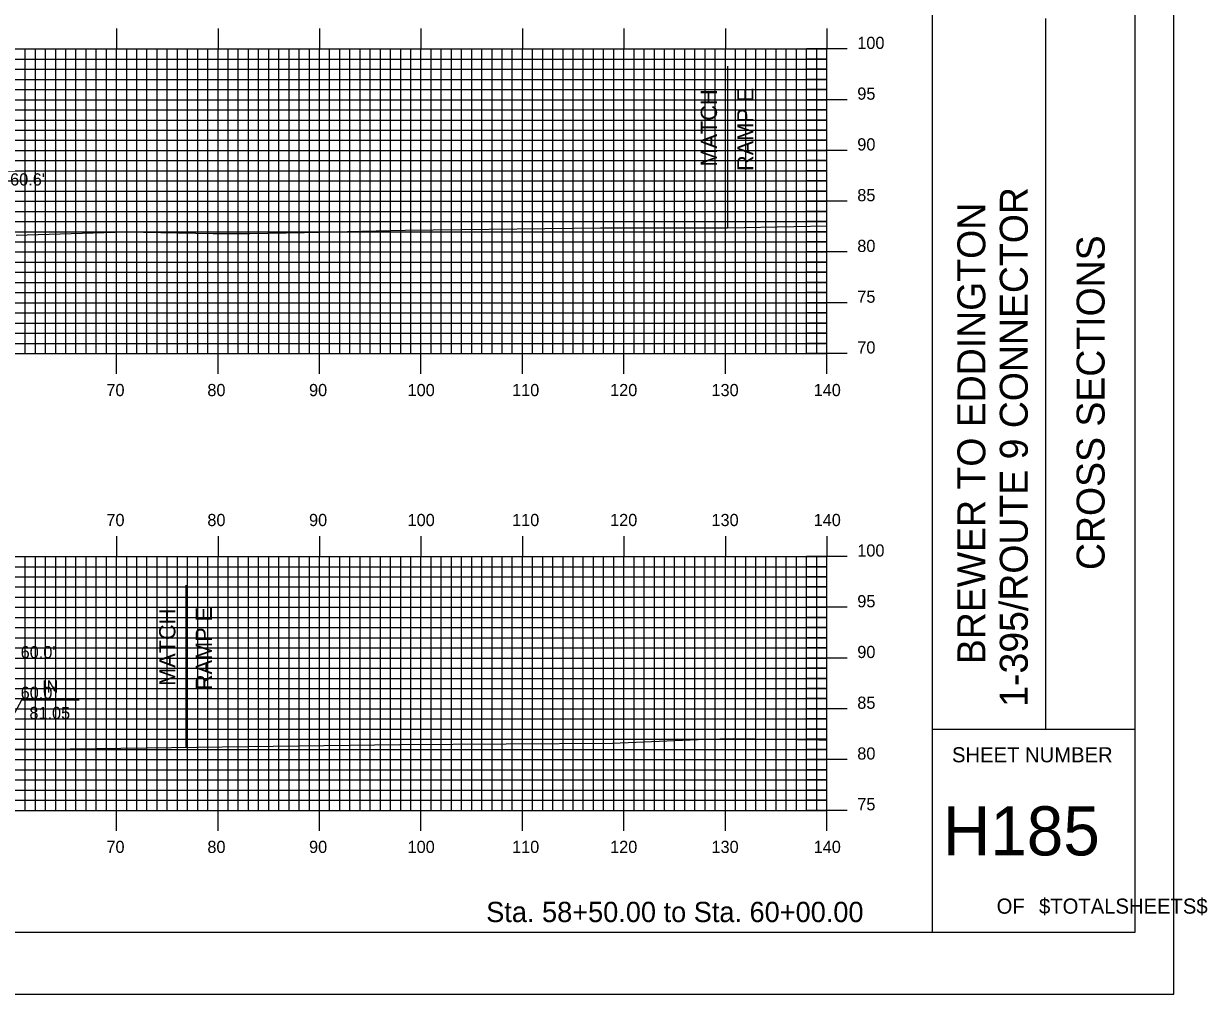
# Model space of a CAD drawing. Extents: x 1757462 to 1757806, y 442591 to 442811.
# Drawn here: x 1757689 to 1757805.6, y 442590.5 to 442686.2 of the extents above; entities that cross this region are included whole.
import ezdxf

# ---------------------------------------------------------------- set-up
doc = ezdxf.new("R2010")
doc.units = 0
for name, color, linetype in [('ANNOTATION', 7, 'Continuous'), ('BORDER', 7, 'Continuous'), ('D_Roadway_SubGrade', 7, 'Continuous'), ('D_Text_Standard', 7, 'Continuous'), ('H_V ANNOTATION', 7, 'Continuous'), ('MAJOR', 7, 'Continuous'), ('MINOR', 7, 'Continuous'), ('PLOT BOUNDARY', 7, 'Continuous'), ('S_Roadway_Centerline', 7, 'Continuous')]:
    doc.layers.add(name, color=color, linetype=linetype)

msp = doc.modelspace()

# ---------------------------------------------------------------- linework, layer by layer
at = {"layer": 'ANNOTATION'}
msp.add_lwpolyline([(1757694.44, 442619.53), (1757688.75, 442619.53), (1757686.11, 442614.72)], dxfattribs=at)
msp.add_lwpolyline([(1757694.44, 442619.53), (1757688.75, 442619.53), (1757686.11, 442614.72)], dxfattribs=at)
at = {"layer": 'BORDER'}
for p, q in [((1757778.51, 442596.67), (1757778.51, 442806.67)), ((1757789.69, 442616.67), (1757789.69, 442686.67)), ((1757778.51, 442616.67), (1757798.51, 442616.67))]:
    msp.add_line(p, q, dxfattribs=at)
msp.add_lwpolyline([(1757478.51, 442596.67), (1757798.51, 442596.67), (1757798.51, 442806.67), (1757478.51, 442806.67)], close=True, dxfattribs=at)
at = {"layer": 'D_Roadway_SubGrade'}
for p, q in [((1757758.32, 442681.99), (1757758.32, 442666.04)), ((1757704.95, 442630.84), (1757704.95, 442614.89))]:
    msp.add_line(p, q, dxfattribs=at)
at = {"layer": 'MAJOR'}
for p, q in [((1757698.11, 442685.67), (1757698.11, 442683.67)), ((1757708.11, 442685.67), (1757708.11, 442683.67)), ((1757718.11, 442685.67), (1757718.11, 442683.67)), ((1757728.11, 442685.67), (1757728.11, 442683.67)), ((1757738.11, 442685.67), (1757738.11, 442683.67)), ((1757748.11, 442685.67), (1757748.11, 442683.67)), ((1757758.11, 442685.67), (1757758.11, 442683.67)), ((1757768.11, 442685.67), (1757768.11, 442683.67)), ((1757488.11, 442683.67), (1757768.11, 442683.67)), ((1757488.11, 442683.67), (1757768.11, 442683.67)), ((1757698.11, 442653.67), (1757698.11, 442683.67)), ((1757708.11, 442653.67), (1757708.11, 442683.67)), ((1757718.11, 442653.67), (1757718.11, 442683.67)), ((1757728.11, 442653.67), (1757728.11, 442683.67)), ((1757738.11, 442653.67), (1757738.11, 442683.67)), ((1757748.11, 442653.67), (1757748.11, 442683.67)), ((1757758.11, 442653.67), (1757758.11, 442683.67)), ((1757770.11, 442683.67), (1757766.11, 442683.67)), ((1757768.11, 442653.67), (1757768.11, 442683.67)), ((1757768.11, 442653.67), (1757768.11, 442683.67)), ((1757488.11, 442678.67), (1757768.11, 442678.67)), ((1757770.11, 442678.67), (1757766.11, 442678.67)), ((1757488.11, 442673.67), (1757768.11, 442673.67)), ((1757770.11, 442673.67), (1757766.11, 442673.67)), ((1757488.11, 442668.67), (1757768.11, 442668.67)), ((1757770.11, 442668.67), (1757766.11, 442668.67)), ((1757488.11, 442663.67), (1757768.11, 442663.67)), ((1757770.11, 442663.67), (1757766.11, 442663.67)), ((1757488.11, 442658.67), (1757768.11, 442658.67)), ((1757770.11, 442658.67), (1757766.11, 442658.67)), ((1757488.11, 442653.67), (1757768.11, 442653.67)), ((1757488.11, 442653.67), (1757768.11, 442653.67)), ((1757698.11, 442651.66), (1757698.11, 442653.67)), ((1757708.11, 442651.66), (1757708.11, 442653.67)), ((1757718.11, 442651.66), (1757718.11, 442653.67)), ((1757728.11, 442651.66), (1757728.11, 442653.67)), ((1757738.11, 442651.66), (1757738.11, 442653.67)), ((1757748.11, 442651.66), (1757748.11, 442653.67)), ((1757758.11, 442651.66), (1757758.11, 442653.67)), ((1757770.11, 442653.67), (1757766.11, 442653.67)), ((1757768.11, 442651.66), (1757768.11, 442653.67)), ((1757698.11, 442635.67), (1757698.11, 442633.67)), ((1757708.11, 442635.67), (1757708.11, 442633.67)), ((1757718.11, 442635.67), (1757718.11, 442633.67)), ((1757728.11, 442635.67), (1757728.11, 442633.67)), ((1757738.11, 442635.67), (1757738.11, 442633.67)), ((1757748.11, 442635.67), (1757748.11, 442633.67)), ((1757758.11, 442635.67), (1757758.11, 442633.67)), ((1757768.11, 442635.67), (1757768.11, 442633.67)), ((1757488.11, 442633.67), (1757768.11, 442633.67)), ((1757488.11, 442633.67), (1757768.11, 442633.67)), ((1757698.11, 442608.67), (1757698.11, 442633.67)), ((1757708.11, 442608.67), (1757708.11, 442633.67)), ((1757718.11, 442608.67), (1757718.11, 442633.67)), ((1757728.11, 442608.67), (1757728.11, 442633.67)), ((1757738.11, 442608.67), (1757738.11, 442633.67)), ((1757748.11, 442608.67), (1757748.11, 442633.67)), ((1757758.11, 442608.67), (1757758.11, 442633.67)), ((1757770.11, 442633.67), (1757766.11, 442633.67)), ((1757768.11, 442608.67), (1757768.11, 442633.67)), ((1757768.11, 442608.67), (1757768.11, 442633.67)), ((1757488.11, 442628.67), (1757768.11, 442628.67)), ((1757770.11, 442628.67), (1757766.11, 442628.67)), ((1757488.11, 442623.67), (1757768.11, 442623.67)), ((1757770.11, 442623.67), (1757766.11, 442623.67)), ((1757488.11, 442618.67), (1757768.11, 442618.67)), ((1757770.11, 442618.67), (1757766.11, 442618.67)), ((1757488.11, 442613.67), (1757768.11, 442613.67)), ((1757770.11, 442613.67), (1757766.11, 442613.67)), ((1757488.11, 442608.67), (1757768.11, 442608.67)), ((1757488.11, 442608.67), (1757768.11, 442608.67)), ((1757698.11, 442606.66), (1757698.11, 442608.67)), ((1757708.11, 442606.66), (1757708.11, 442608.67)), ((1757718.11, 442606.66), (1757718.11, 442608.67)), ((1757728.11, 442606.66), (1757728.11, 442608.67)), ((1757738.11, 442606.66), (1757738.11, 442608.67)), ((1757748.11, 442606.66), (1757748.11, 442608.67)), ((1757758.11, 442606.66), (1757758.11, 442608.67)), ((1757770.11, 442608.67), (1757766.11, 442608.67)), ((1757768.11, 442606.66), (1757768.11, 442608.67))]:
    msp.add_line(p, q, dxfattribs=at)
at = {"layer": 'MINOR'}
for p, q in [((1757689.11, 442653.67), (1757689.11, 442683.67)), ((1757690.11, 442653.67), (1757690.11, 442683.67)), ((1757691.11, 442653.67), (1757691.11, 442683.67)), ((1757692.11, 442653.67), (1757692.11, 442683.67)), ((1757693.11, 442653.67), (1757693.11, 442683.67)), ((1757694.11, 442653.67), (1757694.11, 442683.67)), ((1757695.11, 442653.67), (1757695.11, 442683.67)), ((1757696.11, 442653.67), (1757696.11, 442683.67)), ((1757697.11, 442653.67), (1757697.11, 442683.67)), ((1757699.11, 442653.67), (1757699.11, 442683.67)), ((1757700.11, 442653.67), (1757700.11, 442683.67)), ((1757701.11, 442653.67), (1757701.11, 442683.67)), ((1757702.11, 442653.67), (1757702.11, 442683.67)), ((1757703.11, 442653.67), (1757703.11, 442683.67)), ((1757704.11, 442653.67), (1757704.11, 442683.67)), ((1757705.11, 442653.67), (1757705.11, 442683.67)), ((1757706.11, 442653.67), (1757706.11, 442683.67)), ((1757707.11, 442653.67), (1757707.11, 442683.67)), ((1757709.11, 442653.67), (1757709.11, 442683.67)), ((1757710.11, 442653.67), (1757710.11, 442683.67)), ((1757711.11, 442653.67), (1757711.11, 442683.67)), ((1757712.11, 442653.67), (1757712.11, 442683.67)), ((1757713.11, 442653.67), (1757713.11, 442683.67)), ((1757714.11, 442653.67), (1757714.11, 442683.67)), ((1757715.11, 442653.67), (1757715.11, 442683.67)), ((1757716.11, 442653.67), (1757716.11, 442683.67)), ((1757717.11, 442653.67), (1757717.11, 442683.67)), ((1757719.11, 442653.67), (1757719.11, 442683.67)), ((1757720.11, 442653.67), (1757720.11, 442683.67)), ((1757721.11, 442653.67), (1757721.11, 442683.67)), ((1757722.11, 442653.67), (1757722.11, 442683.67)), ((1757723.11, 442653.67), (1757723.11, 442683.67)), ((1757724.11, 442653.67), (1757724.11, 442683.67)), ((1757725.11, 442653.67), (1757725.11, 442683.67)), ((1757726.11, 442653.67), (1757726.11, 442683.67)), ((1757727.11, 442653.67), (1757727.11, 442683.67)), ((1757729.11, 442653.67), (1757729.11, 442683.67)), ((1757730.11, 442653.67), (1757730.11, 442683.67)), ((1757731.11, 442653.67), (1757731.11, 442683.67)), ((1757732.11, 442653.67), (1757732.11, 442683.67)), ((1757733.11, 442653.67), (1757733.11, 442683.67)), ((1757734.11, 442653.67), (1757734.11, 442683.67)), ((1757735.11, 442653.67), (1757735.11, 442683.67)), ((1757736.11, 442653.67), (1757736.11, 442683.67)), ((1757737.11, 442653.67), (1757737.11, 442683.67)), ((1757739.11, 442653.67), (1757739.11, 442683.67)), ((1757740.11, 442653.67), (1757740.11, 442683.67)), ((1757741.11, 442653.67), (1757741.11, 442683.67)), ((1757742.11, 442653.67), (1757742.11, 442683.67)), ((1757743.11, 442653.67), (1757743.11, 442683.67)), ((1757744.11, 442653.67), (1757744.11, 442683.67)), ((1757745.11, 442653.67), (1757745.11, 442683.67)), ((1757746.11, 442653.67), (1757746.11, 442683.67)), ((1757747.11, 442653.67), (1757747.11, 442683.67)), ((1757749.11, 442653.67), (1757749.11, 442683.67)), ((1757750.11, 442653.67), (1757750.11, 442683.67)), ((1757751.11, 442653.67), (1757751.11, 442683.67)), ((1757752.11, 442653.67), (1757752.11, 442683.67)), ((1757753.11, 442653.67), (1757753.11, 442683.67)), ((1757754.11, 442653.67), (1757754.11, 442683.67)), ((1757755.11, 442653.67), (1757755.11, 442683.67)), ((1757756.11, 442653.67), (1757756.11, 442683.67)), ((1757757.11, 442653.67), (1757757.11, 442683.67)), ((1757759.11, 442653.67), (1757759.11, 442683.67)), ((1757760.11, 442653.67), (1757760.11, 442683.67)), ((1757761.11, 442653.67), (1757761.11, 442683.67)), ((1757762.11, 442653.67), (1757762.11, 442683.67)), ((1757763.11, 442653.67), (1757763.11, 442683.67)), ((1757764.11, 442653.67), (1757764.11, 442683.67)), ((1757765.11, 442653.67), (1757765.11, 442683.67)), ((1757766.11, 442653.67), (1757766.11, 442683.67)), ((1757767.11, 442653.67), (1757767.11, 442683.67)), ((1757488.11, 442682.67), (1757768.11, 442682.67)), ((1757768.11, 442682.67), (1757766.11, 442682.67)), ((1757488.11, 442681.67), (1757768.11, 442681.67)), ((1757768.11, 442681.67), (1757766.11, 442681.67)), ((1757488.11, 442680.67), (1757768.11, 442680.67)), ((1757768.11, 442680.67), (1757766.11, 442680.67)), ((1757488.11, 442679.67), (1757768.11, 442679.67)), ((1757768.11, 442679.67), (1757766.11, 442679.67)), ((1757488.11, 442677.67), (1757768.11, 442677.67)), ((1757768.11, 442677.67), (1757766.11, 442677.67)), ((1757488.11, 442676.67), (1757768.11, 442676.67)), ((1757768.11, 442676.67), (1757766.11, 442676.67)), ((1757488.11, 442675.67), (1757768.11, 442675.67)), ((1757768.11, 442675.67), (1757766.11, 442675.67)), ((1757488.11, 442674.67), (1757768.11, 442674.67)), ((1757768.11, 442674.67), (1757766.11, 442674.67)), ((1757488.11, 442672.67), (1757768.11, 442672.67)), ((1757768.11, 442672.67), (1757766.11, 442672.67)), ((1757488.11, 442671.67), (1757768.11, 442671.67)), ((1757488.11, 442670.67), (1757768.11, 442670.67)), ((1757768.11, 442671.67), (1757766.11, 442671.67)), ((1757768.11, 442670.67), (1757766.11, 442670.67)), ((1757488.11, 442669.67), (1757768.11, 442669.67)), ((1757768.11, 442669.67), (1757766.11, 442669.67)), ((1757488.11, 442667.67), (1757768.11, 442667.67)), ((1757768.11, 442667.67), (1757766.11, 442667.67)), ((1757488.11, 442666.67), (1757768.11, 442666.67)), ((1757768.11, 442666.67), (1757766.11, 442666.67)), ((1757488.11, 442665.67), (1757768.11, 442665.67)), ((1757768.11, 442665.67), (1757766.11, 442665.67)), ((1757488.11, 442664.67), (1757768.11, 442664.67)), ((1757768.11, 442664.67), (1757766.11, 442664.67)), ((1757488.11, 442662.67), (1757768.11, 442662.67)), ((1757768.11, 442662.67), (1757766.11, 442662.67)), ((1757488.11, 442661.67), (1757768.11, 442661.67)), ((1757768.11, 442661.67), (1757766.11, 442661.67)), ((1757488.11, 442660.67), (1757768.11, 442660.67)), ((1757768.11, 442660.67), (1757766.11, 442660.67)), ((1757488.11, 442659.67), (1757768.11, 442659.67)), ((1757768.11, 442659.67), (1757766.11, 442659.67)), ((1757488.11, 442657.67), (1757768.11, 442657.67)), ((1757488.11, 442656.67), (1757768.11, 442656.67)), ((1757768.11, 442657.67), (1757766.11, 442657.67)), ((1757768.11, 442656.67), (1757766.11, 442656.67)), ((1757488.11, 442655.67), (1757768.11, 442655.67)), ((1757768.11, 442655.67), (1757766.11, 442655.67)), ((1757488.11, 442654.67), (1757768.11, 442654.67)), ((1757768.11, 442654.67), (1757766.11, 442654.67)), ((1757689.11, 442608.67), (1757689.11, 442633.67)), ((1757690.11, 442608.67), (1757690.11, 442633.67)), ((1757691.11, 442608.67), (1757691.11, 442633.67)), ((1757692.11, 442608.67), (1757692.11, 442633.67)), ((1757693.11, 442608.67), (1757693.11, 442633.67)), ((1757694.11, 442608.67), (1757694.11, 442633.67)), ((1757695.11, 442608.67), (1757695.11, 442633.67)), ((1757696.11, 442608.67), (1757696.11, 442633.67)), ((1757697.11, 442608.67), (1757697.11, 442633.67)), ((1757699.11, 442608.67), (1757699.11, 442633.67)), ((1757700.11, 442608.67), (1757700.11, 442633.67)), ((1757701.11, 442608.67), (1757701.11, 442633.67)), ((1757702.11, 442608.67), (1757702.11, 442633.67)), ((1757703.11, 442608.67), (1757703.11, 442633.67)), ((1757704.11, 442608.67), (1757704.11, 442633.67)), ((1757705.11, 442608.67), (1757705.11, 442633.67)), ((1757706.11, 442608.67), (1757706.11, 442633.67)), ((1757707.11, 442608.67), (1757707.11, 442633.67)), ((1757709.11, 442608.67), (1757709.11, 442633.67)), ((1757710.11, 442608.67), (1757710.11, 442633.67)), ((1757711.11, 442608.67), (1757711.11, 442633.67)), ((1757712.11, 442608.67), (1757712.11, 442633.67)), ((1757713.11, 442608.67), (1757713.11, 442633.67)), ((1757714.11, 442608.67), (1757714.11, 442633.67)), ((1757715.11, 442608.67), (1757715.11, 442633.67)), ((1757716.11, 442608.67), (1757716.11, 442633.67)), ((1757717.11, 442608.67), (1757717.11, 442633.67)), ((1757719.11, 442608.67), (1757719.11, 442633.67)), ((1757720.11, 442608.67), (1757720.11, 442633.67)), ((1757721.11, 442608.67), (1757721.11, 442633.67)), ((1757722.11, 442608.67), (1757722.11, 442633.67)), ((1757723.11, 442608.67), (1757723.11, 442633.67)), ((1757724.11, 442608.67), (1757724.11, 442633.67)), ((1757725.11, 442608.67), (1757725.11, 442633.67)), ((1757726.11, 442608.67), (1757726.11, 442633.67)), ((1757727.11, 442608.67), (1757727.11, 442633.67)), ((1757729.11, 442608.67), (1757729.11, 442633.67)), ((1757730.11, 442608.67), (1757730.11, 442633.67)), ((1757731.11, 442608.67), (1757731.11, 442633.67)), ((1757732.11, 442608.67), (1757732.11, 442633.67)), ((1757733.11, 442608.67), (1757733.11, 442633.67)), ((1757734.11, 442608.67), (1757734.11, 442633.67)), ((1757735.11, 442608.67), (1757735.11, 442633.67)), ((1757736.11, 442608.67), (1757736.11, 442633.67)), ((1757737.11, 442608.67), (1757737.11, 442633.67)), ((1757739.11, 442608.67), (1757739.11, 442633.67)), ((1757740.11, 442608.67), (1757740.11, 442633.67)), ((1757741.11, 442608.67), (1757741.11, 442633.67)), ((1757742.11, 442608.67), (1757742.11, 442633.67)), ((1757743.11, 442608.67), (1757743.11, 442633.67)), ((1757744.11, 442608.67), (1757744.11, 442633.67)), ((1757745.11, 442608.67), (1757745.11, 442633.67)), ((1757746.11, 442608.67), (1757746.11, 442633.67)), ((1757747.11, 442608.67), (1757747.11, 442633.67)), ((1757749.11, 442608.67), (1757749.11, 442633.67)), ((1757750.11, 442608.67), (1757750.11, 442633.67)), ((1757751.11, 442608.67), (1757751.11, 442633.67)), ((1757752.11, 442608.67), (1757752.11, 442633.67)), ((1757753.11, 442608.67), (1757753.11, 442633.67)), ((1757754.11, 442608.67), (1757754.11, 442633.67)), ((1757755.11, 442608.67), (1757755.11, 442633.67)), ((1757756.11, 442608.67), (1757756.11, 442633.67)), ((1757757.11, 442608.67), (1757757.11, 442633.67)), ((1757759.11, 442608.67), (1757759.11, 442633.67)), ((1757760.11, 442608.67), (1757760.11, 442633.67)), ((1757761.11, 442608.67), (1757761.11, 442633.67)), ((1757762.11, 442608.67), (1757762.11, 442633.67)), ((1757763.11, 442608.67), (1757763.11, 442633.67)), ((1757764.11, 442608.67), (1757764.11, 442633.67)), ((1757765.11, 442608.67), (1757765.11, 442633.67)), ((1757766.11, 442608.67), (1757766.11, 442633.67)), ((1757767.11, 442608.67), (1757767.11, 442633.67)), ((1757488.11, 442632.67), (1757768.11, 442632.67)), ((1757768.11, 442632.67), (1757766.11, 442632.67)), ((1757488.11, 442631.67), (1757768.11, 442631.67)), ((1757768.11, 442631.67), (1757766.11, 442631.67)), ((1757488.11, 442630.67), (1757768.11, 442630.67)), ((1757768.11, 442630.67), (1757766.11, 442630.67)), ((1757488.11, 442629.67), (1757768.11, 442629.67)), ((1757768.11, 442629.67), (1757766.11, 442629.67)), ((1757488.11, 442627.67), (1757768.11, 442627.67)), ((1757768.11, 442627.67), (1757766.11, 442627.67)), ((1757488.11, 442626.67), (1757768.11, 442626.67)), ((1757768.11, 442626.67), (1757766.11, 442626.67)), ((1757488.11, 442625.67), (1757768.11, 442625.67)), ((1757768.11, 442625.67), (1757766.11, 442625.67)), ((1757488.11, 442624.67), (1757768.11, 442624.67)), ((1757768.11, 442624.67), (1757766.11, 442624.67)), ((1757488.11, 442622.67), (1757768.11, 442622.67)), ((1757488.11, 442621.67), (1757768.11, 442621.67)), ((1757768.11, 442622.67), (1757766.11, 442622.67)), ((1757768.11, 442621.67), (1757766.11, 442621.67)), ((1757488.11, 442620.67), (1757768.11, 442620.67)), ((1757768.11, 442620.67), (1757766.11, 442620.67)), ((1757488.11, 442619.67), (1757768.11, 442619.67)), ((1757768.11, 442619.67), (1757766.11, 442619.67)), ((1757488.11, 442617.67), (1757768.11, 442617.67)), ((1757768.11, 442617.67), (1757766.11, 442617.67)), ((1757488.11, 442616.67), (1757768.11, 442616.67)), ((1757768.11, 442616.67), (1757766.11, 442616.67)), ((1757488.11, 442615.67), (1757768.11, 442615.67)), ((1757488.11, 442614.67), (1757768.11, 442614.67)), ((1757768.11, 442615.67), (1757766.11, 442615.67)), ((1757768.11, 442614.67), (1757766.11, 442614.67)), ((1757488.11, 442612.67), (1757768.11, 442612.67)), ((1757768.11, 442612.67), (1757766.11, 442612.67)), ((1757488.11, 442611.67), (1757768.11, 442611.67)), ((1757768.11, 442611.67), (1757766.11, 442611.67)), ((1757488.11, 442610.67), (1757768.11, 442610.67)), ((1757768.11, 442610.67), (1757766.11, 442610.67)), ((1757488.11, 442609.67), (1757768.11, 442609.67)), ((1757768.11, 442609.67), (1757766.11, 442609.67))]:
    msp.add_line(p, q, dxfattribs=at)
at = {"layer": 'PLOT BOUNDARY'}
msp.add_lwpolyline([(1757462.32, 442590.55), (1757802.32, 442590.55), (1757802.32, 442810.55), (1757462.32, 442810.55)], close=True, dxfattribs=at)
at = {"layer": 'S_Roadway_Centerline'}
for points in [[(1757688.21, 442665.32), (1757699.07, 442665.67), (1757707.64, 442665.48), (1757711.25, 442665.5), (1757716.6, 442665.59), (1757726.56, 442665.81), (1757734.82, 442665.92), (1757745.81, 442666.05), (1757748.27, 442666.05), (1757758.32, 442666.04), (1757764.85, 442666.17), (1757768.11, 442666.25)], [(1757488.11, 442613.68), (1757501.17, 442613.77), (1757507.94, 442613.71), (1757514.36, 442613.67), (1757553.81, 442614.57), (1757553.88, 442614.57), (1757554, 442614.57), (1757581.3, 442614.24), (1757598.31, 442614.07), (1757601.32, 442614.11), (1757627.79, 442614.8), (1757645.88, 442614.86), (1757665.07, 442614.91), (1757687.39, 442614.71), (1757688.63, 442614.72), (1757691.05, 442614.71), (1757726.03, 442615.16), (1757736.49, 442615.21), (1757747, 442615.3), (1757756.19, 442615.67), (1757758.95, 442615.74), (1757767.31, 442615.61), (1757768.11, 442615.6)]]:
    msp.add_lwpolyline(points, dxfattribs=at)

# ---------------------------------------------------------------- texts
at = {"layer": 'ANNOTATION'}
for s, p in [('MATCH', (1757757.28, 442672.08)), ('RAMP E', (1757760.88, 442671.65)), ('RAMP E', (1757707.51, 442620.51)), ('MATCH', (1757703.91, 442620.93))]:
    msp.add_text(s, height=1.6, rotation=90, dxfattribs=at).set_placement(p)
for s, p in [('IN', (1757690.77, 442620.26)), ('IN', (1757690.77, 442620.26)), ('81.05', (1757689.52, 442617.66)), ('81.05', (1757689.52, 442617.66))]:
    msp.add_text(s, height=1.2, dxfattribs=at).set_placement(p)
at = {"layer": 'BORDER'}
for s, p in [('1-395/ROUTE 9 CONNECTOR', (1757787.91, 442618.87)), ('BREWER TO EDDINGTON', (1757783.73, 442623.07)), ('CROSS SECTIONS', (1757795.48, 442632.34))]:
    msp.add_text(s, height=2.7557, rotation=90, dxfattribs=at).set_placement(p)
for s, height, p in [('SHEET NUMBER', 1.4905, (1757780.44, 442613.4)), ('H185', 4.839, (1757779.54, 442604.23)), ('OF', 1.491, (1757784.84, 442598.49)), ('$TOTALSHEETS$', 1.4905, (1757789.02, 442598.49))]:
    msp.add_text(s, height=height, dxfattribs=at).set_placement(p)
at = {"layer": 'D_Text_Standard'}
for s, p in [("60.6'", (1757687.62, 442670.22)), ("60.0'", (1757688.66, 442623.65)), ("60.0'", (1757688.66, 442619.65))]:
    msp.add_text(s, height=1.2, dxfattribs=at).set_placement(p)
at = {"layer": 'H_V ANNOTATION'}
for s, height, p in [('100', 1.2, (1757771.11, 442683.67)), ('95', 1.2, (1757771.11, 442678.67)), ('90', 1.2, (1757771.11, 442673.67)), ('85', 1.2, (1757771.11, 442668.67)), ('80', 1.2, (1757771.11, 442663.67)), ('75', 1.2, (1757771.11, 442658.67)), ('70', 1.2, (1757771.11, 442653.67)), ('70', 1.2, (1757697.11, 442649.47)), ('80', 1.2, (1757707.06, 442649.47)), ('90', 1.2, (1757717.08, 442649.47)), ('100', 1.2, (1757726.79, 442649.47)), ('110', 1.2, (1757737.09, 442649.47)), ('120', 1.2, (1757746.75, 442649.47)), ('130', 1.2, (1757756.74, 442649.47)), ('140', 1.2, (1757766.81, 442649.47)), ('70', 1.2, (1757697.11, 442636.67)), ('80', 1.2, (1757707.06, 442636.67)), ('90', 1.2, (1757717.08, 442636.67)), ('100', 1.2, (1757726.79, 442636.67)), ('110', 1.2, (1757737.09, 442636.67)), ('120', 1.2, (1757746.75, 442636.67)), ('130', 1.2, (1757756.74, 442636.67)), ('140', 1.2, (1757766.81, 442636.67)), ('100', 1.2, (1757771.11, 442633.67)), ('95', 1.2, (1757771.11, 442628.67)), ('90', 1.2, (1757771.11, 442623.67)), ('85', 1.2, (1757771.11, 442618.67)), ('80', 1.2, (1757771.11, 442613.67)), ('75', 1.2, (1757771.11, 442608.67)), ('70', 1.2, (1757697.11, 442604.47)), ('80', 1.2, (1757707.06, 442604.47)), ('90', 1.2, (1757717.08, 442604.47)), ('100', 1.2, (1757726.79, 442604.47)), ('110', 1.2, (1757737.09, 442604.47)), ('120', 1.2, (1757746.75, 442604.47)), ('130', 1.2, (1757756.74, 442604.47)), ('140', 1.2, (1757766.81, 442604.47)), ('Sta. 58+50.00 to Sta. 60+00.00', 2.0004, (1757734.54, 442597.66))]:
    msp.add_text(s, height=height, dxfattribs=at).set_placement(p)

doc.saveas('drawing.dxf')
